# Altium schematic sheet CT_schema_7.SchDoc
size 278 x 170 mm
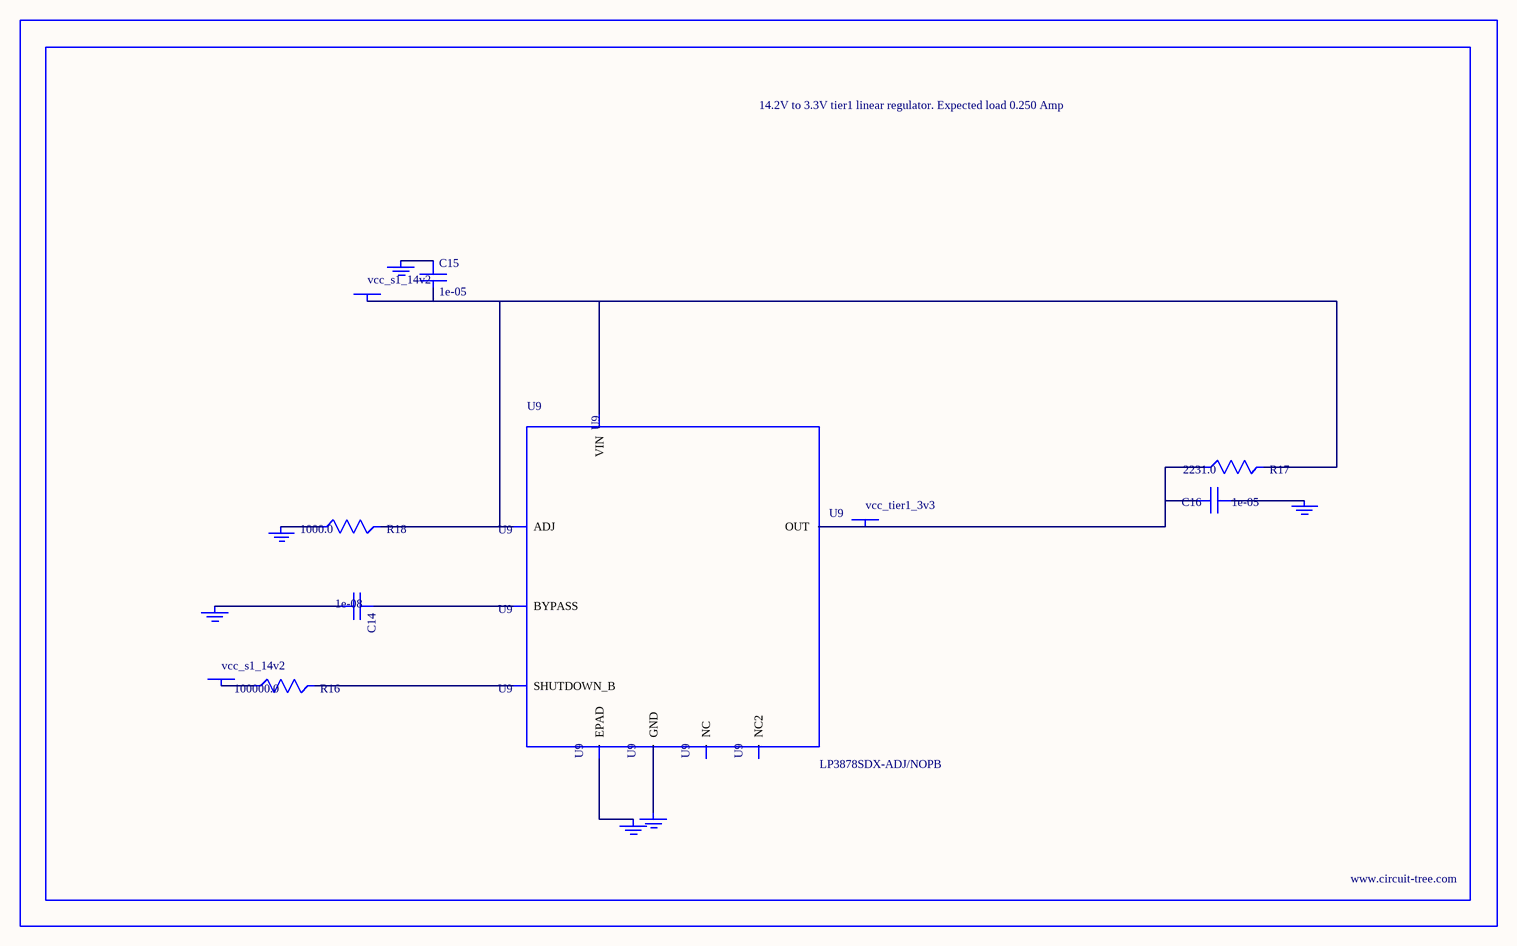
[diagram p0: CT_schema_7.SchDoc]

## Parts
BORDER6  (no value)
C14  1e-08  [C0402]
C15  1e-05  [C1210]
C16  1e-05  [C1210]
GND_INSTANCE_6_0  (no value)
GND_INSTANCE_6_1  (no value)
GND_INSTANCE_6_2  (no value)
GND_INSTANCE_6_3  (no value)
GND_INSTANCE_6_4  (no value)
GND_INSTANCE_6_5  (no value)
POWER_INSTANCE_6_0  vcc_s1_14v2
POWER_INSTANCE_6_1  vcc_s1_14v2
POWER_INSTANCE_6_2  vcc_tier1_3v3
R16  100000.0  [R0603]
R17  2231.0  [R0603]
R18  1000.0  [R0603]
U9  LP3878SDX-ADJ/NOPB  [WSON-8]

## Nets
NetC14_1: C14.1 U9.1(BYPASS)
NetC14_2: C14.2 GND_INSTANCE_6_0.0(GND)
NetC15_1: C15.1 GND_INSTANCE_6_1.0(GND)
NetC15_2: C15.2 POWER_INSTANCE_6_0.0(PWR) R17.2 R18.2 U9.4(VIN) U9.6(ADJ)
NetC16_1: C16.1 GND_INSTANCE_6_2.0(GND)
NetC16_2: C16.2 POWER_INSTANCE_6_2.0(PWR) R17.1 U9.5(OUT)
NetGND_INSTANCE_6_3_0: GND_INSTANCE_6_3.0(GND) R18.1
NetGND_INSTANCE_6_4_0: GND_INSTANCE_6_4.0(GND) U9.PAD(EPAD)
NetGND_INSTANCE_6_5_0: GND_INSTANCE_6_5.0(GND) U9.3(GND)
NetPOWER_INSTANCE_6_1_0: POWER_INSTANCE_6_1.0(PWR) R16.1
NetR16_2: R16.2 U9.8(SHUTDOWN_B)

Not connected (* = marked no-connect by the designer): U9 2(NC) 7(NC2)

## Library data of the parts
BORDER6 = BORDER_PAGE6
C14 = C0402C103K3RAC
C15 = C1210C106K5PACTU
C16 = GRM32DR61E106MA12L
GND_INSTANCE_6_0-GND_INSTANCE_6_5 = GND
POWER_INSTANCE_6_0-POWER_INSTANCE_6_2 = PWR
R16 = RC0603JR-07100KL
R17 = R17
R18 = RC0603JR-071KL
